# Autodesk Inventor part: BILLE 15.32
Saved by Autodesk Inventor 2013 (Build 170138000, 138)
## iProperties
Created: 2012-12
Part Number: BILLE 15.32
Material: Générique
Document SubType Name: Modeling
Designer: jost thierry
Density: 1 g/cm^3
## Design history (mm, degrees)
node "BILLE 15.321"
node "BILLE 15.32"
node "Base1"
